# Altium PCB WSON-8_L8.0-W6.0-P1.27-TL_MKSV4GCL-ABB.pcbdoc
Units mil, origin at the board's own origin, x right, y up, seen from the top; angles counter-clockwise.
Board outline 845 x 755 mil, 2 copper layers (Top Layer, Bottom Layer), stack 2.757 mil thick; 1 components, 0 nets, 14 pads, 0 vias.
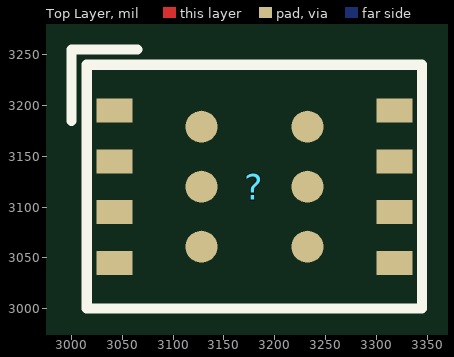
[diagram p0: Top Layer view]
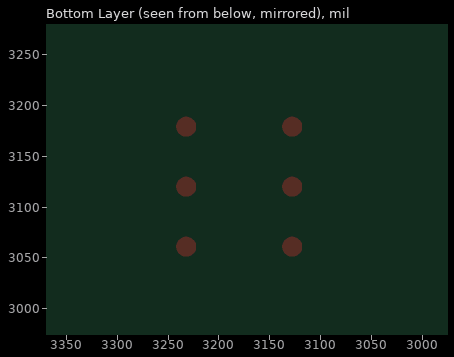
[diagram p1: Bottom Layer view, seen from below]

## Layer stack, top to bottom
Top Solder Mask Layer: solder mask 0.394, Dk 3.3
Top Layer: signal copper 1.379
Bottom Layer: signal copper 1.378
Bottom Solder Mask Layer: solder mask 0.394, Dk 3.3

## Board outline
3595,2750 2750,2750 2750,3505 3595,3505

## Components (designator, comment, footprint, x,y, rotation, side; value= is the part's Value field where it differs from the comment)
? "WSON-8_L8.0-W6.0-P1.27-TL_MKSV4GCL-ABB" WSON-8_L8.0-W6.0-P1.27-TL_MKSV4GCL-ABB 3180.01,3120 r0 top

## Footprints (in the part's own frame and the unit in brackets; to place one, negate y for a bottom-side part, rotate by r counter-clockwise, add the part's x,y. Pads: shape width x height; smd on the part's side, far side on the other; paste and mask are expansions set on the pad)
WSON-8_L8.0-W6.0-P1.27-TL_MKSV4GCL-ABB [mm]
  rect 0.9x0.6 smd paste+0 mask+0.051: 1(-3.5,1.905) 2(-3.5,0.635) 3(-3.5,-0.635) 4(-3.5,-1.905) 5(3.5,-1.905) 6(3.5,-0.635) 7(3.5,0.635) 8(3.5,1.905)
  round 0.8 smd paste+0 mask+0.051: 9(-1.325,-1.5) 9(-1.325,0) 9(-1.325,1.5) 9(1.325,-1.5) 9(1.325,0) 9(1.325,1.5)
  Top Layer circle w0.25: c1.325,-1.5 r0.125
  Top Layer circle w0.25: c-1.325,-1.5 r0.125
  Top Layer circle w0.25: c1.325,0 r0.125
  Top Layer circle w0.25: c-1.325,0 r0.125
  Top Layer circle w0.25: c1.325,1.5 r0.125
  Top Layer circle w0.25: c-1.325,1.5 r0.125
  silkscreen extent -4.57,-3.05 4.19,3.43

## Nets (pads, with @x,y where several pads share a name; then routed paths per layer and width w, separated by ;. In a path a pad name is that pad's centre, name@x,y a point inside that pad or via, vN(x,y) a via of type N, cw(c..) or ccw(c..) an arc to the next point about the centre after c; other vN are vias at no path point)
pads on no net: ?.1 ?.2 ?.3 ?.4 ?.5 ?.6 ?.7 ?.8 ?.9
